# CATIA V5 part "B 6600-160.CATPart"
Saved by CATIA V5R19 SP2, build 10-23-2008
Part number: B 6600-160
Bounding box of the stored display mesh (mm): x -59.975 to 59.975, y -59.975 to 59.975, z 0 to 460
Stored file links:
  C:\Users\Bora\Desktop\3D Katı model\B serisi\B 6600\B 6600-160.CATPart
  C:\Program Files\Dassault Systemes\B19\intel_a\reffiles\standard\MetricThickPitch.txt
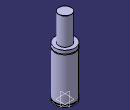
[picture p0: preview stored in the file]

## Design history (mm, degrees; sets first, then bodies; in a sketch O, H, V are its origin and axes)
Body1 (main body)
  Sketch1 on yz-plane, origin (0, 0, 0), H (0, 1, 0), V (0, 0, 1)
    point P3 (37.5, 459)
    point P5 (37.5, 459)
    point P10 (60, 272)
    point P11 (60, 277)
    point P13 (60, 277)
    point P14 (60, 272)
    line L1 (60, 0) -> (60, 8)
    line L2 (37.5, 459) -> (37.5, 297)
    arc A1 centre (36.5, 459) radius 1 from (37.5, 459) to (36.5, 460) ccw
    line L3 (56, 13) -> (56, 8)
    line L4 (60, 13) -> (60, 272)
    line L5 (60, 277) -> (60, 297)
    arc A2 centre (60, 274.5) radius 2.5 from (60, 277) to (60, 272) ccw
    line L6 (36.5, 460) -> (0, 460)
    point P15 (0, 460)
    line L7 (37.5, 297) -> (60, 297)
    line L8 (0, 0) -> (60, 0)
    line L9 (56, 13) -> (60, 13)
    line L10 (56, 8) -> (60, 8)
    coincidence: P15 V, P3 P5, P10 P14, P11 P13
    tangency: L6 A1
    horizontal: L7 H, L8 H, L9 H, L10 H
  Shaft1: profile Sketch1, axis Sketch1.V, angle 360
  Sketch2 on face of Shaft1 from Sketch1.L8, origin (0, 0, 0), H (1, 0, 0), V (0, -1, 0)
    point P1 (40, 0)
    distance P1 V = 40
  Hole1: placed by Sketch2, at (40, 0, 0) direction (0, 0, 1), diameter 8.376, depth 16, threaded "M10", thread diameter 10, thread depth 16, pitch 1.5
  CircPattern1: of Hole1, instances 4, angular step 90, axis from xy-plane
